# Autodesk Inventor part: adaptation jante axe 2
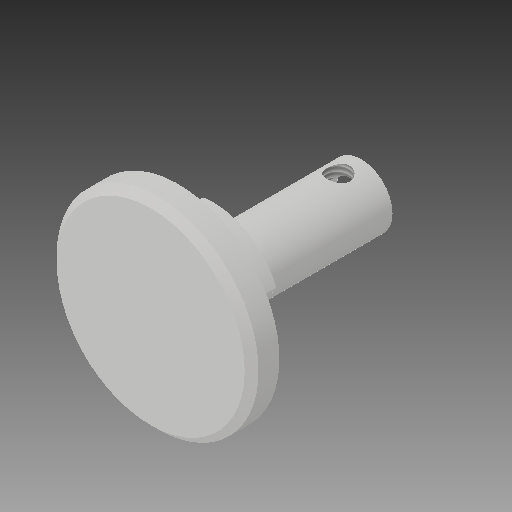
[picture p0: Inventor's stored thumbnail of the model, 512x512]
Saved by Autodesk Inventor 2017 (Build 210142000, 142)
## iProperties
Part Number: adaptation jante axe 2
Material: Générique
Document SubType Name: Modeling
Designer: ficho
Density: 1 g/cm^3
Appearance: Par défaut
Mass: 3.89833 g
Surface Area: 31.3537 cm^2
Volume: 3.89833 cm^3
Author: ficho
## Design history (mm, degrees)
sketch "Esquisse1"
  geometry: L1 (13.235, -4)-(23.235, -4) reference; L2 (21.235, -37.25)-(15.235, -37.25) reference; L3 (18.235, -10)-(18.235, -4); L4 (22.735, -30.25)-(21.25, -30.25); L5 (21.25, -30.25)-(21.25, -17.75) reference; L6 (20.735, -17.25)-(15.735, -17.25) reference; L7 (21.25, -17.75)-(21.25, -11.603); L8 (21.25, -11.603)-(18.235, -10); L9 (23.235, -4)-(32.735, -4); L10 (32.735, -4)-(32.735, -1); L11 (31.735, 0)-(18.235, 0); L12 (18.235, 0)-(18.235, -4); L13 (25.489, -4.868)-(28.36, -4.868) reference; L14 (31.735, 0)-(32.735, -1); L15 (22.735, -30.25)-(22.735, -4); L16 (23.235, -4)-(22.735, -4); 2 further points
  constraints: 24 end point, 6 perpendicular, 3 point on line, 2 vertical, 1 horizontal, 1 midpoint, 3 other
  dimensions: "d0" = 118 deg angle of L8 L7; "d1" = 4 distance of L9.end point (32.735, 0); "d3" = 1 distance of L11.start point (32.735, 0); "d4" = 1 distance of L10.end point (32.735, 0) (= d3); "d7" = 14.5 distance between parallel lines of L10 L12; "d22" = 7 distance between parallel lines of L4 L2; "d28" = 4.5 distance between parallel lines of L15 L3; "d37" = 10 distance from line of L11 L3.start
revolve "Révolution1" sketch "Esquisse1" stored, may be unused: angle "d2" = 90 deg
sketch "Esquisse2"
  geometry: L1 (-0.852, 0.298)-(0, 0); L2 (0, 0)-(0.168, 0.883); A1 r 10.125 centre (0, 0) between (2.491, 9.814) and (-9.744, 2.75) reference; A2 r 6.75 centre (0, 0) between (1.367, 6.61) and (-6.408, 2.122) reference; A3 r 9.75 centre (0, 0) between (1.307, 9.662) and (-9.017, 3.709); A4 r 8.75 centre (0, 0) between (1.173, 8.671) and (-8.092, 3.329); A5 r 0.5 centre (1.24, 9.167) between (1.173, 8.671) and (1.307, 9.662); A6 r 0.5 centre (-8.554, 3.519) between (-9.017, 3.709) and (-8.092, 3.329); 5 further points
  constraints: 9 point on circle, 4 centre point, 4 end point, 1 coincident
  dimensions: "d31" = 17.5 diameter of A4; "d32" = 19.5 diameter of A3
extrude "Extrusion1" join sketch "Esquisse2" distance "d8" = 5; taper "d9" = 0 deg
pattern_circular "Réseau circulaire1" dims angle "d14" = 360 deg
node "Plan de construction5"
sketch "Esquisse3"
  geometry: L1 (-23.175, 0)-(19.175, 0) reference; L2 (-13.125, 5)-(-13.125, -5) reference; L3 (13.125, -5)-(13.125, 5) reference; L4 (13.125, -4.5)-(13.125, 4.5) reference; L5 (-13.125, 4.5)-(-13.125, -4.5) reference; L6 (13.125, -4.5)-(13.125, 4.5) reference; L7 (13.125, 0)-(-17.125, 0); L8 (-17.125, -13.5)-(-17.125, 13.5) reference; C1 r 1.65 at (9.825, 0); 1 further point
  constraints: 2 end point, 2 midpoint, 1 centre point, 1 point on line
  dimensions: "d30" = 3.3 distance from line of L3 C1.centre
extrude "Extrusion2" cut sketch "Esquisse3" stored distance "d18" = 5; taper "d19" = 0 deg
chamfer "Chanfrein1" distance "d24" = 0.5; stored, may be unused: second distance "d25" = 2, angle "d26" = 45 deg
feature "Filetage2" dims "d35" = 10, "d36" = 0
node "Solide1"
node "Référence1"
node "Référence2"
node "Référence3"
node "Référence4"
node "Référence5"
node "Référence6"
node "Boucle projetée1"
node "Boucle projetée2"
